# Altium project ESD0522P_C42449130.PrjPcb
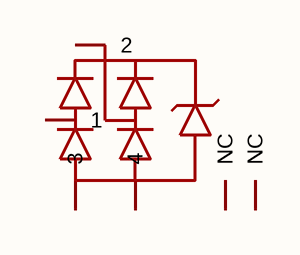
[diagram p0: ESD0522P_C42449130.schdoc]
1 sheet, 1 parts. Net scope: global (net labels, ports and power ports of the same name join across sheets).

## Sheet ESD0522P_C42449130.schdoc
size 127 x 101 mm

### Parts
D?  esd0522p_c42449130  [UDFN-6_L1.6-W1.0-P0.50-BL]  (value not drawn)

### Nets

Not connected (* = marked no-connect by the designer): D? 1 2 3 4 5(NC) 6(NC)

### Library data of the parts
D? = esd0522p_c42449130: 反向截止电压(Vrwm):5V;峰值脉冲电流(Ipp):4.5A@8/20us;峰值脉冲功率(Ppp):100W@8/20us;; Manufacturer: JSMSEMI(杰盛微); AddInBom: yes; ModelId: 72e436cde92e4fc88fe22225bfa188c8; ModelName: UDFN-6_L1.6-W1.0-H0.5-P0.50-BL; ModelTransform: 62.992,40.1574,0,0,0,0,1.964,-0.1,0; Reverse Stand-Off Voltage (Vrwm): 5V; Reverse Leakage Current (Ir): 1uA; Number of Channels: 双路; level of protection: IEC 61000-4-2; Type: ESD; Junction Capacitance: 0.5pF；0.9pF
